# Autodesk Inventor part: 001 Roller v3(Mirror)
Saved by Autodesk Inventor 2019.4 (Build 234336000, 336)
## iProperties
Created: 2020-06
Part Number: 001 Roller v3(Mirror)
Material: Generic
Document SubType Name: Modeling
Designer: Administrator
Density: 1 g/cm^3
Appearance: Default
Title: 001 Roller v3(Mirror)
Author: Administrator
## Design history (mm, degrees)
